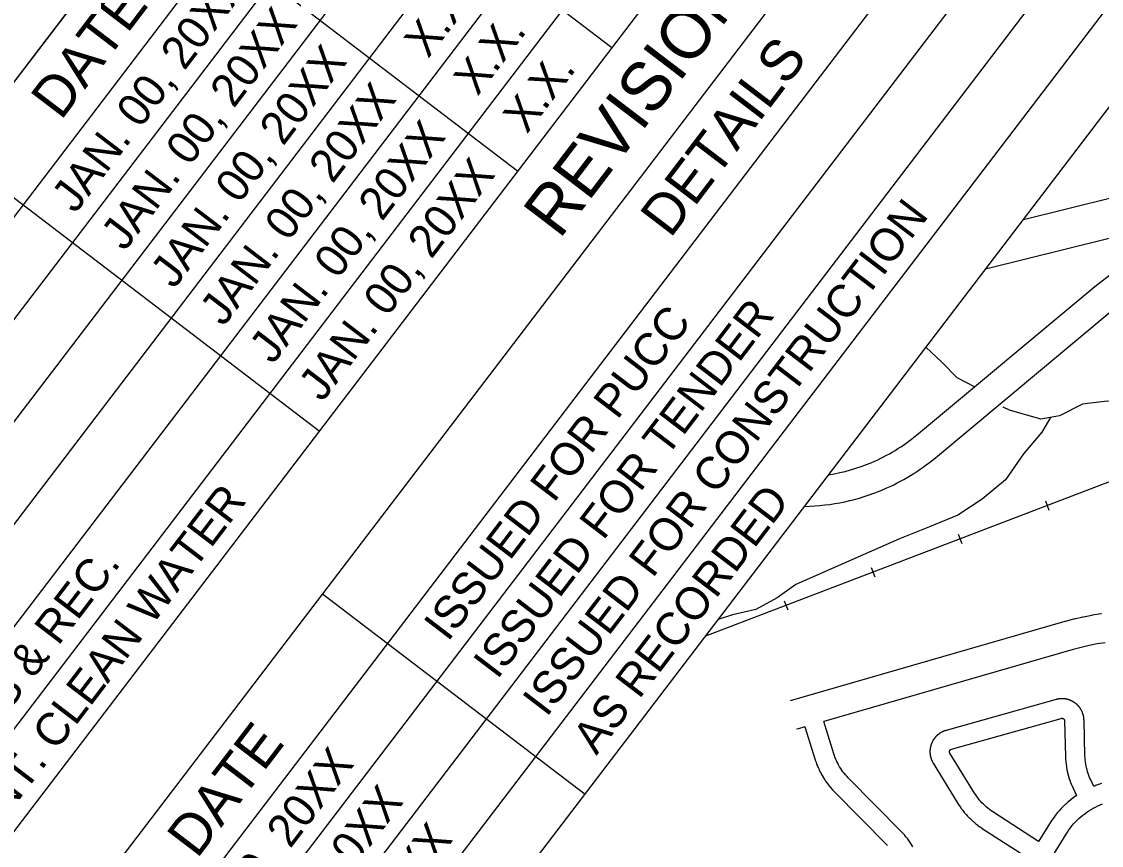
# Model space of a CAD drawing. Extents: x 599744 to 600217, y 4827560 to 4828065.
# Drawn here: x 599974.43 to 600007.45, y 4827993.33 to 4828018.52 of the extents above; entities that cross this region are included whole.
import ezdxf

# ---------------------------------------------------------------- set-up
doc = ezdxf.new("R2010")
doc.units = 0
for name, color, linetype in [('Default', 7, 'Continuous'), ('G-ANNO-KEYP', 7, 'Continuous'), ('G-ANNO-TTLB-TEXT', 7, 'Continuous'), ('G-TTLB-OTLN', 7, 'Continuous')]:
    doc.layers.add(name, color=color, linetype=linetype)

msp = doc.modelspace()

# ---------------------------------------------------------------- linework, layer by layer
at = {"layer": 'G-ANNO-KEYP'}
for p, q in [((600001.8, 4828005.879), (600007.257, 4828010.424)), ((600002.376, 4828005.187), (600007.817, 4828009.72)), ((600007.454, 4828004.357), (599995.35, 4827999.732)), ((600005.741, 4828003.863), (600005.848, 4828003.582)), ((600003.078, 4828002.845), (600003.185, 4828002.565)), ((600000.416, 4828001.828), (600000.523, 4828001.548)), ((599997.753, 4828000.811), (599997.86, 4828000.531))]:
    msp.add_line(p, q, dxfattribs=at)
for points in [[(600005.072, 4828012.476), (600027.218, 4828017.966), (600028.959, 4828018.431), (600030.677, 4828018.956), (600032.375, 4828019.541), (600034.051, 4828020.187), (600035.703, 4828020.892), (600037.329, 4828021.656), (600038.687, 4828022.354)], [(600027.512, 4828016.804), (600003.91, 4828010.952)], [(600007.257, 4828010.424), (600007.707, 4828010.767), (600008.284, 4828011.123), (600008.472, 4828011.208), (600008.656, 4828011.269), (600008.728, 4828011.287)], [(600003.571, 4828007.355), (600003.043, 4828007.634), (600002.571, 4828008.104), (600002.088, 4828008.564)], [(600013.426, 4828007.215), (600013.152, 4828007.153), (600012.61, 4828007.077), (600012.325, 4828006.943), (600011.962, 4828006.889), (600011.49, 4828006.884), (600011.067, 4828006.93), (600010.62, 4828006.798), (600009.927, 4828006.766), (600009.535, 4828006.689), (600009.066, 4828006.681), (600008.701, 4828006.773), (600008.202, 4828006.864), (600007.632, 4828006.912), (600006.873, 4828006.824), (600006.168, 4828006.464), (600005.605, 4828006.366), (600004.645, 4828006.636), (600004.449, 4828006.734)], [(600005.901, 4828006.417), (600005.637, 4828005.965), (600005.076, 4828005.309), (600004.521, 4828004.51), (600003.807, 4828003.92), (600003.068, 4828003.425), (600002.192, 4828003.07), (600001.277, 4828002.703), (599998.11, 4828001.314), (599997.538, 4828000.904), (599996.886, 4828000.543), (599996.169, 4828000.383), (599995.733, 4828000.234)], [(600013.487, 4828005.851), (600013.047, 4828005.795), (600012.605, 4828005.73), (600012.167, 4828005.655), (600011.731, 4828005.576), (600011.292, 4828005.487), (600010.859, 4828005.393), (600010.426, 4828005.29), (600009.994, 4828005.177), (600009.566, 4828005.06), (600009.139, 4828004.935), (600008.713, 4828004.799), (600008.291, 4828004.66), (600007.872, 4828004.514), (600007.454, 4828004.357), (599995.35, 4827999.732)], [(599997.945, 4827997.76), (600006.35, 4828000.187), (600006.356, 4828000.188), (600006.358, 4828000.189), (600006.613, 4828000.258), (600006.627, 4828000.26), (600006.629, 4828000.262), (600006.887, 4828000.321), (600006.901, 4828000.324), (600006.903, 4828000.325), (600007.163, 4828000.376), (600007.178, 4828000.378), (600007.178, 4828000.378), (600007.44, 4828000.42), (600007.455, 4828000.422)], [(600007.574, 4827999.53), (600007.327, 4827999.491), (600007.083, 4827999.444), (600006.84, 4827999.387), (600006.595, 4827999.321), (599998.962, 4827997.118)], [(600006.142, 4827997.809), (600006.142, 4827997.809), (600006.132, 4827997.807), (600006.118, 4827997.805), (600006.118, 4827997.804), (600006.108, 4827997.803), (600006.095, 4827997.8), (600006.094, 4827997.799), (600006.085, 4827997.797), (600006.072, 4827997.794), (600006.071, 4827997.793), (600006.067, 4827997.792), (600002.703, 4827996.847), (600002.702, 4827996.846), (600002.697, 4827996.845), (600002.685, 4827996.841), (600002.683, 4827996.84), (600002.675, 4827996.838), (600002.662, 4827996.834), (600002.66, 4827996.832), (600002.652, 4827996.83), (600002.639, 4827996.825), (600002.637, 4827996.823), (600002.63, 4827996.821), (600002.617, 4827996.816), (600002.614, 4827996.814), (600002.608, 4827996.812), (600002.596, 4827996.806), (600002.592, 4827996.804), (600002.586, 4827996.802), (600002.574, 4827996.796), (600002.57, 4827996.793), (600002.565, 4827996.791), (600002.553, 4827996.784), (600002.549, 4827996.781), (600002.544, 4827996.779), (600002.532, 4827996.772), (600002.528, 4827996.768), (600002.523, 4827996.766), (600002.512, 4827996.759), (600002.507, 4827996.755), (600002.504, 4827996.753), (600002.493, 4827996.746), (600002.487, 4827996.741), (600002.484, 4827996.739), (600002.473, 4827996.731), (600002.468, 4827996.726), (600002.465, 4827996.725), (600002.455, 4827996.716), (600002.449, 4827996.711)], [(600006.541, 4827997.751), (600006.538, 4827997.752), (600006.531, 4827997.756), (600006.519, 4827997.761), (600006.515, 4827997.762), (600006.509, 4827997.766), (600006.496, 4827997.771), (600006.493, 4827997.771), (600006.487, 4827997.774), (600006.474, 4827997.779), (600006.47, 4827997.779), (600006.464, 4827997.782), (600006.451, 4827997.787), (600006.446, 4827997.787), (600006.441, 4827997.79), (600006.428, 4827997.793), (600006.423, 4827997.794), (600006.418, 4827997.796), (600006.405, 4827997.799), (600006.399, 4827997.8), (600006.395, 4827997.802), (600006.381, 4827997.805), (600006.375, 4827997.805), (600006.371, 4827997.807), (600006.358, 4827997.809), (600006.351, 4827997.809), (600006.347, 4827997.81), (600006.334, 4827997.812), (600006.326, 4827997.812), (600006.323, 4827997.814), (600006.31, 4827997.815), (600006.302, 4827997.815), (600006.299, 4827997.816), (600006.286, 4827997.817), (600006.277, 4827997.816), (600006.275, 4827997.817), (600006.262, 4827997.818), (600006.253, 4827997.817), (600006.251, 4827997.818), (600006.238, 4827997.818), (600006.228, 4827997.817), (600006.227, 4827997.817), (600006.214, 4827997.817), (600006.204, 4827997.816), (600006.203, 4827997.816), (600006.19, 4827997.815), (600006.18, 4827997.814), (600006.179, 4827997.814), (600006.166, 4827997.813), (600006.163, 4827997.812), (600006.155, 4827997.811), (600006.142, 4827997.809)], [(600006.83, 4827997.486), (600006.823, 4827997.498), (600006.819, 4827997.502), (600006.817, 4827997.507), (600006.81, 4827997.518), (600006.805, 4827997.523), (600006.804, 4827997.527), (600006.796, 4827997.538), (600006.791, 4827997.543), (600006.79, 4827997.546), (600006.782, 4827997.557), (600006.777, 4827997.562), (600006.775, 4827997.565), (600006.767, 4827997.575), (600006.761, 4827997.581), (600006.76, 4827997.584), (600006.751, 4827997.594), (600006.745, 4827997.6), (600006.744, 4827997.602), (600006.735, 4827997.611), (600006.728, 4827997.617), (600006.727, 4827997.619), (600006.718, 4827997.628), (600006.71, 4827997.635), (600006.71, 4827997.636), (600006.7, 4827997.645), (600006.692, 4827997.651), (600006.692, 4827997.652), (600006.682, 4827997.661), (600006.674, 4827997.667), (600006.674, 4827997.667), (600006.663, 4827997.675), (600006.661, 4827997.677), (600006.655, 4827997.682), (600006.644, 4827997.69), (600006.643, 4827997.69), (600006.635, 4827997.696), (600006.624, 4827997.704), (600006.623, 4827997.704), (600006.615, 4827997.71), (600006.604, 4827997.717), (600006.603, 4827997.717), (600006.595, 4827997.722), (600006.583, 4827997.729), (600006.581, 4827997.729), (600006.574, 4827997.734), (600006.562, 4827997.741), (600006.56, 4827997.741), (600006.553, 4827997.745), (600006.541, 4827997.751)], [(600006.999, 4827995.703), (600006.986, 4827995.763), (600006.975, 4827995.824), (600006.966, 4827995.884), (600006.959, 4827995.946), (600006.955, 4827996.007), (600006.952, 4827996.072), (600006.923, 4827997.161), (600006.923, 4827997.166), (600006.923, 4827997.166), (600006.922, 4827997.18), (600006.922, 4827997.19), (600006.922, 4827997.19), (600006.921, 4827997.204), (600006.92, 4827997.214), (600006.92, 4827997.214), (600006.918, 4827997.227), (600006.918, 4827997.23), (600006.917, 4827997.238), (600006.915, 4827997.252), (600006.915, 4827997.252), (600006.913, 4827997.262), (600006.911, 4827997.275), (600006.91, 4827997.276), (600006.908, 4827997.286), (600006.905, 4827997.299), (600006.905, 4827997.3), (600006.903, 4827997.309), (600006.899, 4827997.322), (600006.898, 4827997.323), (600006.897, 4827997.332), (600006.893, 4827997.345), (600006.891, 4827997.347), (600006.889, 4827997.355), (600006.885, 4827997.368), (600006.883, 4827997.37), (600006.881, 4827997.378), (600006.877, 4827997.39), (600006.875, 4827997.393), (600006.873, 4827997.4), (600006.867, 4827997.413), (600006.865, 4827997.416), (600006.863, 4827997.422), (600006.858, 4827997.434), (600006.855, 4827997.438), (600006.853, 4827997.444), (600006.847, 4827997.456), (600006.843, 4827997.46), (600006.842, 4827997.465), (600006.835, 4827997.477), (600006.832, 4827997.481), (600006.83, 4827997.486)], [(599998.386, 4827996.952), (599998.195, 4827996.896), (599998.125, 4827996.882)], [(599998.386, 4827996.952), (599998.701, 4827995.947), (599998.702, 4827995.946), (599998.703, 4827995.942), (599998.726, 4827995.874), (599998.727, 4827995.872), (599998.729, 4827995.865), (599998.754, 4827995.798), (599998.756, 4827995.795), (599998.757, 4827995.789), (599998.784, 4827995.723), (599998.787, 4827995.72), (599998.788, 4827995.713), (599998.818, 4827995.648), (599998.82, 4827995.645), (599998.822, 4827995.639), (599998.853, 4827995.575), (599998.856, 4827995.572), (599998.858, 4827995.566), (599998.892, 4827995.503), (599998.895, 4827995.499), (599998.896, 4827995.494), (599998.932, 4827995.433), (599998.936, 4827995.429), (599998.937, 4827995.424), (599998.975, 4827995.364), (599998.979, 4827995.359), (599998.981, 4827995.355), (599999.02, 4827995.296), (599999.025, 4827995.291), (599999.026, 4827995.288), (599999.068, 4827995.23), (599999.073, 4827995.225), (599999.074, 4827995.222), (599999.118, 4827995.165), (599999.123, 4827995.16), (599999.124, 4827995.157), (599999.17, 4827995.103), (599999.175, 4827995.097), (599999.176, 4827995.095), (599999.224, 4827995.042), (599999.23, 4827995.036), (599999.231, 4827995.034), (599999.28, 4827994.983), (599999.283, 4827994.98), (599999.283, 4827994.979), (600000.916, 4827993.325)], [(600001.688, 4827993.284), (600001.657, 4827993.338), (600001.653, 4827993.342), (600001.652, 4827993.347), (600001.619, 4827993.4), (600001.615, 4827993.405), (600001.613, 4827993.409), (600001.579, 4827993.461), (600001.574, 4827993.465), (600001.573, 4827993.469), (600001.536, 4827993.52), (600001.532, 4827993.525), (600001.53, 4827993.528), (600001.492, 4827993.577), (600001.487, 4827993.583), (600001.486, 4827993.585), (600001.446, 4827993.633), (600001.44, 4827993.639), (600001.439, 4827993.641), (600001.398, 4827993.688), (600001.392, 4827993.693), (600001.391, 4827993.695), (600001.348, 4827993.74), (600001.344, 4827993.743), (600001.344, 4827993.744), (599999.711, 4827995.398), (599999.667, 4827995.444), (599999.627, 4827995.49), (599999.588, 4827995.537), (599999.55, 4827995.585), (599999.514, 4827995.635), (599999.48, 4827995.685), (599999.448, 4827995.737), (599999.417, 4827995.79), (599999.389, 4827995.844), (599999.362, 4827995.899), (599999.337, 4827995.954), (599999.313, 4827996.011), (599999.292, 4827996.068), (599999.272, 4827996.128), (599998.962, 4827997.118)], [(600002.81, 4827996.188), (600002.81, 4827996.191), (600002.81, 4827996.193), (600002.81, 4827996.196), (600002.81, 4827996.199), (600002.81, 4827996.201), (600002.81, 4827996.204), (600002.81, 4827996.207), (600002.811, 4827996.209), (600002.811, 4827996.212), (600002.812, 4827996.215), (600002.812, 4827996.217), (600002.813, 4827996.22), (600002.814, 4827996.223), (600002.815, 4827996.225), (600002.816, 4827996.227), (600002.817, 4827996.23), (600002.818, 4827996.232), (600002.82, 4827996.235), (600002.821, 4827996.237), (600002.822, 4827996.239), (600002.824, 4827996.241), (600002.825, 4827996.244), (600002.827, 4827996.246), (600002.829, 4827996.248), (600002.831, 4827996.25), (600002.832, 4827996.252), (600002.834, 4827996.253), (600002.837, 4827996.255), (600002.838, 4827996.257), (600002.841, 4827996.258), (600002.843, 4827996.26), (600002.845, 4827996.261), (600002.848, 4827996.263), (600002.85, 4827996.264), (600002.852, 4827996.265), (600002.855, 4827996.266), (600002.857, 4827996.268), (600002.86, 4827996.268), (600002.862, 4827996.269), (600002.867, 4827996.271), (600006.226, 4827997.215), (600006.231, 4827997.217), (600006.234, 4827997.217), (600006.236, 4827997.218), (600006.239, 4827997.218), (600006.242, 4827997.218), (600006.245, 4827997.219), (600006.247, 4827997.219), (600006.25, 4827997.219)], [(600006.25, 4827997.219), (600006.253, 4827997.219), (600006.255, 4827997.219), (600006.258, 4827997.218), (600006.261, 4827997.218), (600006.263, 4827997.218), (600006.266, 4827997.217), (600006.268, 4827997.216), (600006.271, 4827997.215), (600006.274, 4827997.215), (600006.276, 4827997.214), (600006.279, 4827997.213), (600006.281, 4827997.212), (600006.284, 4827997.21), (600006.286, 4827997.209), (600006.288, 4827997.208), (600006.291, 4827997.206), (600006.293, 4827997.205), (600006.295, 4827997.203), (600006.297, 4827997.202), (600006.299, 4827997.2), (600006.301, 4827997.198), (600006.303, 4827997.196), (600006.305, 4827997.194), (600006.307, 4827997.192), (600006.308, 4827997.19), (600006.31, 4827997.188), (600006.311, 4827997.186), (600006.313, 4827997.183), (600006.314, 4827997.181), (600006.316, 4827997.179), (600006.317, 4827997.176), (600006.318, 4827997.174), (600006.319, 4827997.171), (600006.32, 4827997.169), (600006.321, 4827997.167), (600006.322, 4827997.164), (600006.322, 4827997.161), (600006.323, 4827997.159), (600006.324, 4827997.156), (600006.324, 4827997.153), (600006.324, 4827997.151), (600006.324, 4827997.148), (600006.325, 4827997.142), (600006.353, 4827996.053), (600006.354, 4827996.049), (600006.353, 4827996.048), (600006.357, 4827995.976), (600006.357, 4827995.967), (600006.357, 4827995.966), (600006.363, 4827995.894)], [(600002.449, 4827996.711), (600002.446, 4827996.709), (600002.436, 4827996.701), (600002.431, 4827996.695), (600002.429, 4827996.694), (600002.419, 4827996.684), (600002.413, 4827996.678), (600002.411, 4827996.677), (600002.402, 4827996.668), (600002.396, 4827996.661), (600002.395, 4827996.66), (600002.385, 4827996.65), (600002.379, 4827996.643), (600002.378, 4827996.642), (600002.37, 4827996.632), (600002.363, 4827996.624), (600002.363, 4827996.624), (600002.355, 4827996.614), (600002.352, 4827996.61), (600002.348, 4827996.605), (600002.34, 4827996.594), (600002.34, 4827996.594), (600002.334, 4827996.586), (600002.326, 4827996.575), (600002.326, 4827996.574), (600002.32, 4827996.566), (600002.313, 4827996.555), (600002.313, 4827996.553), (600002.308, 4827996.546), (600002.301, 4827996.534), (600002.301, 4827996.532), (600002.296, 4827996.525), (600002.289, 4827996.513), (600002.289, 4827996.511), (600002.284, 4827996.504), (600002.279, 4827996.492), (600002.278, 4827996.489), (600002.274, 4827996.482), (600002.268, 4827996.47), (600002.268, 4827996.467), (600002.264, 4827996.461), (600002.259, 4827996.448), (600002.259, 4827996.444), (600002.255, 4827996.438), (600002.251, 4827996.426), (600002.25, 4827996.421), (600002.247, 4827996.415), (600002.243, 4827996.403), (600002.242, 4827996.398), (600002.24, 4827996.393), (600002.236, 4827996.38), (600002.236, 4827996.375)], [(600002.236, 4827996.375), (600002.233, 4827996.37), (600002.23, 4827996.357), (600002.23, 4827996.351), (600002.227, 4827996.346), (600002.225, 4827996.333), (600002.224, 4827996.327), (600002.223, 4827996.323), (600002.22, 4827996.31), (600002.22, 4827996.303), (600002.219, 4827996.3), (600002.217, 4827996.286), (600002.217, 4827996.279), (600002.215, 4827996.276), (600002.214, 4827996.262), (600002.214, 4827996.254), (600002.213, 4827996.252), (600002.212, 4827996.239), (600002.212, 4827996.23), (600002.212, 4827996.228), (600002.211, 4827996.215), (600002.211, 4827996.206), (600002.211, 4827996.204), (600002.211, 4827996.191), (600002.211, 4827996.181), (600002.211, 4827996.18), (600002.211, 4827996.167), (600002.212, 4827996.157), (600002.212, 4827996.156), (600002.213, 4827996.143), (600002.214, 4827996.132), (600002.214, 4827996.132), (600002.215, 4827996.119), (600002.216, 4827996.114), (600002.217, 4827996.109), (600002.219, 4827996.095), (600002.219, 4827996.095), (600002.22, 4827996.085), (600002.223, 4827996.072), (600002.223, 4827996.071), (600002.225, 4827996.061), (600002.228, 4827996.048), (600002.228, 4827996.047), (600002.23, 4827996.038), (600002.233, 4827996.025), (600002.234, 4827996.023), (600002.236, 4827996.015), (600002.24, 4827996.002), (600002.241, 4827996), (600002.243, 4827995.992)], [(600002.243, 4827995.992), (600002.247, 4827995.979), (600002.249, 4827995.977), (600002.251, 4827995.969), (600002.255, 4827995.957), (600002.257, 4827995.954), (600002.259, 4827995.947), (600002.264, 4827995.934), (600002.267, 4827995.931), (600002.268, 4827995.925), (600002.274, 4827995.912), (600002.277, 4827995.909), (600002.279, 4827995.903), (600002.284, 4827995.891), (600002.287, 4827995.887), (600002.289, 4827995.882), (600002.296, 4827995.87), (600002.299, 4827995.866), (600002.301, 4827995.86), (600002.308, 4827995.849), (600002.31, 4827995.847), (600002.31, 4827995.845), (600003.066, 4827994.614), (600003.068, 4827994.612), (600003.068, 4827994.61), (600003.107, 4827994.549), (600003.112, 4827994.544), (600003.113, 4827994.54), (600003.154, 4827994.481), (600003.159, 4827994.476), (600003.16, 4827994.472), (600003.203, 4827994.414), (600003.208, 4827994.409), (600003.209, 4827994.406), (600003.254, 4827994.349), (600003.26, 4827994.344), (600003.261, 4827994.341), (600003.308, 4827994.286), (600003.314, 4827994.281), (600003.315, 4827994.279), (600003.364, 4827994.225), (600003.37, 4827994.219), (600003.371, 4827994.218), (600003.421, 4827994.166), (600003.428, 4827994.16), (600003.429, 4827994.159), (600003.481, 4827994.109), (600003.488, 4827994.102), (600003.489, 4827994.102), (600003.543, 4827994.054), (600003.55, 4827994.047), (600003.551, 4827994.047)], [(600006.294, 4827994.528), (600006.288, 4827994.522), (600006.287, 4827994.521), (600006.225, 4827994.458), (600006.219, 4827994.451), (600006.218, 4827994.451), (600006.159, 4827994.386), (600006.153, 4827994.379), (600006.152, 4827994.378), (600006.095, 4827994.312), (600006.089, 4827994.304), (600006.088, 4827994.304), (600006.034, 4827994.235), (600006.032, 4827994.232), (600006.028, 4827994.227), (600005.975, 4827994.156), (600005.975, 4827994.156), (600005.969, 4827994.148), (600005.92, 4827994.076), (600005.919, 4827994.075), (600005.914, 4827994.067), (600005.867, 4827993.993), (600005.866, 4827993.992), (600005.864, 4827993.989), (600005.535, 4827993.455), (600004.138, 4827994.354), (600004.084, 4827994.391), (600004.034, 4827994.426), (600003.984, 4827994.465), (600003.937, 4827994.504), (600003.891, 4827994.546), (600003.845, 4827994.589), (600003.802, 4827994.633), (600003.76, 4827994.679), (600003.72, 4827994.726), (600003.682, 4827994.774), (600003.644, 4827994.824), (600003.609, 4827994.875), (600003.575, 4827994.93), (600002.822, 4827996.156), (600002.82, 4827996.16), (600002.818, 4827996.162), (600002.817, 4827996.165), (600002.816, 4827996.167), (600002.815, 4827996.17), (600002.814, 4827996.172), (600002.813, 4827996.175), (600002.812, 4827996.177), (600002.812, 4827996.18), (600002.811, 4827996.183), (600002.811, 4827996.186), (600002.81, 4827996.188)], [(600006.363, 4827995.894), (600006.364, 4827995.884), (600006.364, 4827995.884), (600006.372, 4827995.813), (600006.372, 4827995.809), (600006.373, 4827995.803), (600006.383, 4827995.731), (600006.384, 4827995.731), (600006.385, 4827995.721), (600006.398, 4827995.651), (600006.398, 4827995.65), (600006.4, 4827995.641), (600006.415, 4827995.57), (600006.416, 4827995.569), (600006.418, 4827995.56), (600006.435, 4827995.491), (600006.436, 4827995.489), (600006.438, 4827995.481), (600006.458, 4827995.412), (600006.459, 4827995.41), (600006.461, 4827995.402), (600006.483, 4827995.334), (600006.485, 4827995.332), (600006.487, 4827995.324), (600006.512, 4827995.257), (600006.513, 4827995.254), (600006.515, 4827995.247), (600006.542, 4827995.181), (600006.544, 4827995.178), (600006.546, 4827995.171), (600006.576, 4827995.106), (600006.577, 4827995.104), (600006.578, 4827995.101), (600006.693, 4827994.854), (600006.672, 4827994.84), (600006.667, 4827994.836), (600006.663, 4827994.834), (600006.592, 4827994.783), (600006.587, 4827994.778), (600006.584, 4827994.777), (600006.514, 4827994.723), (600006.509, 4827994.718), (600006.506, 4827994.717), (600006.439, 4827994.661), (600006.433, 4827994.655), (600006.431, 4827994.654), (600006.365, 4827994.596), (600006.359, 4827994.59), (600006.358, 4827994.589), (600006.294, 4827994.528)], [(600007.462, 4827995.221), (600007.454, 4827995.219), (600007.37, 4827995.192), (600007.368, 4827995.191), (600007.361, 4827995.189), (600007.278, 4827995.159), (600007.275, 4827995.157), (600007.268, 4827995.155), (600007.222, 4827995.136), (600007.121, 4827995.352), (600007.095, 4827995.41), (600007.072, 4827995.468), (600007.051, 4827995.525), (600007.032, 4827995.584), (600007.015, 4827995.643), (600006.999, 4827995.703)], [(600005.885, 4827992.881), (600006.372, 4827993.673), (600006.416, 4827993.74), (600006.46, 4827993.804), (600006.505, 4827993.866), (600006.554, 4827993.927), (600006.604, 4827993.986), (600006.656, 4827994.043), (600006.711, 4827994.098), (600006.767, 4827994.152), (600006.825, 4827994.203), (600006.884, 4827994.253), (600006.946, 4827994.3), (600007.009, 4827994.345), (600007.073, 4827994.388), (600007.139, 4827994.429), (600007.206, 4827994.468), (600007.274, 4827994.504), (600007.344, 4827994.537), (600007.415, 4827994.569), (600007.487, 4827994.598)], [(600003.551, 4827994.047), (600003.606, 4827994.001), (600003.613, 4827993.995), (600003.614, 4827993.994), (600003.672, 4827993.95), (600003.672, 4827993.95), (600003.68, 4827993.944), (600003.739, 4827993.901), (600003.739, 4827993.901), (600003.747, 4827993.895), (600003.807, 4827993.855), (600003.808, 4827993.855), (600003.812, 4827993.852), (600005.221, 4827992.945)]]:
    msp.add_lwpolyline(points, dxfattribs=at)
for radius, start, end in [(5.551, 293.0812, 309.711), (6.451, 293.0812, 309.7112), (5.55, 278.9151, 293.0813), (6.451, 271.0954, 293.0811)]:
    msp.add_arc((599998.254, 4828010.149), radius, start, end, dxfattribs=at)
at = {"layer": 'G-TTLB-OTLN'}
for p, q in [((600000.656, 4828051.367), (599962.201, 4828000.96)), ((599962.203, 4828000.958), (600000.658, 4828051.366)), ((600002.644, 4828049.851), (599964.188, 4827999.443)), ((600004.155, 4828048.698), (599965.699, 4827998.291)), ((600005.665, 4828047.546), (599967.21, 4827997.138)), ((600007.176, 4828046.394), (599968.72, 4827995.986)), ((600008.686, 4828045.241), (599970.231, 4827994.834)), ((600010.197, 4828044.089), (599971.741, 4827993.681)), ((600011.708, 4828042.936), (599973.252, 4827992.529)), ((600014.172, 4828041.056), (599975.717, 4827990.648)), ((600016.16, 4828039.54), (599977.704, 4827989.132)), ((600017.67, 4828038.387), (599979.215, 4827987.98)), ((600019.181, 4828037.235), (599980.725, 4827986.827)), ((600020.692, 4828036.082), (599982.236, 4827985.675)), ((599981.429, 4828026.164), (599992.48, 4828017.733)), ((599978.548, 4828022.387), (599989.599, 4828013.956)), ((599972.482, 4828014.437), (599983.534, 4828006.006)), ((599983.633, 4828001.026), (599991.663, 4827994.899))]:
    msp.add_line(p, q, dxfattribs=at)
msp.add_lwpolyline([(599983.747, 4827984.522), (600022.202, 4828034.93), (600058.02, 4828007.605), (600019.565, 4827957.197)], close=True, dxfattribs=at)

# ---------------------------------------------------------------- texts
at = {"layer": 'Default'}
msp.add_text('THIS DRAWING SAMPLE IS INTENDED TO ILLUSTRATE THE NEW CAD STANDARDS FOR ROAD WORKS AND SHOULD BE USED FOR REFERENCE PURPOSES ONLY.', height=3.5, rotation=52.6603, dxfattribs=at).set_placement((599752.419, 4827739.237))
at = {"layer": 'G-ANNO-TTLB-TEXT'}
for s, height, rotation, p in [('REVISIONS', 1.5, 52.6603, (599990.881, 4828011.843)), ('JAN. 00, 20XX', 1, 52.6602, (599976.069, 4828012.627)), ('DATE', 1.25, 52.6603, (599975.631, 4828015.475)), ('X.X.', 1, 52.6602, (599986.86, 4828017.373)), ('JAN. 00, 20XX', 1, 52.6602, (599977.58, 4828011.475)), ('X.X.', 1, 52.6602, (599988.372, 4828016.22)), ('JAN. 00, 20XX', 1, 52.6602, (599979.091, 4828010.322)), ('DETAILS', 1.25, 52.6603, (599994.269, 4828011.872)), ('X.X.', 1, 52.6602, (599989.882, 4828015.068)), ('JAN. 00, 20XX', 1, 52.6602, (599980.602, 4828009.17)), ('JAN. 00, 20XX', 1, 52.6602, (599982.113, 4828008.016)), ('JAN. 00, 20XX', 1, 52.6602, (599983.623, 4828006.864)), ('ISSUED FOR CONSTRUCTION', 1, 52.6602, (599990.484, 4827997.228)), ('ISSUED FOR TENDER', 1, 52.6602, (599988.974, 4827998.38)), ('ISSUED FOR PUCC', 1, 52.6602, (599987.464, 4827999.532)), ('ONT. CLEAN WATER ', 1, 52.6603, (599973.318, 4827993.355)), ('AS RECORDED', 1, 52.6602, (599992.008, 4827996.065)), ('PARKS & REC.', 1, 52.6603, (599971.808, 4827994.507)), ('DATE', 1.25, 52.6603, (599979.794, 4827992.899)), ('JAN. 00, 20XX', 1, 52.6602, (599979.307, 4827988.839)), ('JAN. 00, 20XX', 1, 52.6602, (599980.817, 4827987.687)), ('JAN. 00, 20XX', 1, 52.6603, (599982.326, 4827986.535))]:
    msp.add_text(s, height=height, rotation=rotation, dxfattribs=at).set_placement(p)

doc.saveas('drawing.dxf')
